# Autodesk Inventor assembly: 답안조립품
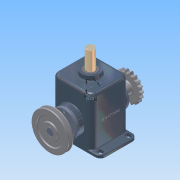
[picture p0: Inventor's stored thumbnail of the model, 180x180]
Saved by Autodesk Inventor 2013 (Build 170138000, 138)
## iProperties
Created: 2015-03
Part Number: 답안조립품
Document SubType Name: Assembly
Designer: Administrator
Mass: 8579.28 g
Surface Area: 4386.42 cm^2
Volume: 1982.54 cm^3
Density: 4.32742 g/cm^3
Author: Administrator
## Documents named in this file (15)
- C:\Documents and Settings\Administrator\바탕 화면\350305V1020\답안조립품.iam
- C:\Documents and Settings\Administrator\바탕 화면\350305V1020\본체.ipt
- C:\Documents and Settings\Administrator\바탕 화면\350305V1020\베어링 6205.ipt
- C:\Documents and Settings\Administrator\바탕 화면\350305V1020\커버.ipt
- C:\Documents and Settings\Administrator\바탕 화면\350305V1020\M4x0.5.ipt
- C:\Documents and Settings\Administrator\바탕 화면\350305V1020\편심축.ipt
- C:\Documents and Settings\Administrator\바탕 화면\350305V1020\멈춤링.ipt
- C:\Documents and Settings\Administrator\바탕 화면\350305V1020\오일실.ipt
- C:\Documents and Settings\Administrator\바탕 화면\350305V1020\키 8x8.ipt
- C:\Documents and Settings\Administrator\바탕 화면\350305V1020\V-벨트풀리.ipt
- C:\Documents and Settings\Administrator\바탕 화면\350305V1020\멈춤나사 M5x0.5.ipt
- C:\Documents and Settings\Administrator\바탕 화면\350305V1020\체인 스프로킷.ipt
- C:\Documents and Settings\Administrator\바탕 화면\350305V1020\7-가변스프링.ipt
- C:\Documents and Settings\Administrator\바탕 화면\350305V1020\부시.ipt
- C:\Documents and Settings\Administrator\바탕 화면\350305V1020\슬라이드.ipt
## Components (9 placed, 4 different names)
1. V-벨트풀리:1 — 플러쉬:3, 각도:2
2. 5-체인 스프로킷:1 — 플러쉬:4, 각도:3
3. 7-가변스프링:1
4. M4x0.5:2
5. M4x0.5:3
6. M4x0.5:4
7. M4x0.5:5
8. M4x0.5:6
9. M4x0.5:7
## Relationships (4: Flush 2, Angle 2)
- 플러쉬:3 [Flush]: V-벨트풀리:1
- 각도:2 [Angle]: V-벨트풀리:1
- 플러쉬:4 [Flush]: 5-체인 스프로킷:1
- 각도:3 [Angle]: 5-체인 스프로킷:1
